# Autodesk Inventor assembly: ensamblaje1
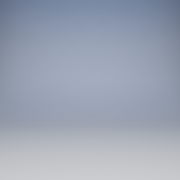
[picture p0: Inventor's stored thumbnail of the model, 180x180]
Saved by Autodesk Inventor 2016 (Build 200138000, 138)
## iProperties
Created: 2016-06
Part Number: ensamblaje1
Material: Genérico
Document SubType Name: Assembly
Designer: adm
Author: adm
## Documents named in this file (1)
- C:\Users\adm\Desktop\el ultimo\ensamblaje1.iam
